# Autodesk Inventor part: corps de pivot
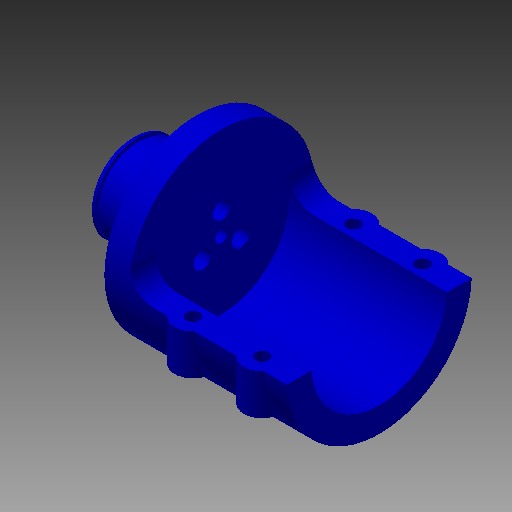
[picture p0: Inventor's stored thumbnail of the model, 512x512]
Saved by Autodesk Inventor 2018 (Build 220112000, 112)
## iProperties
Created: 2015-03
Part Number: corps de pivot
Material: Générique
Document SubType Name: Modeling
Designer: tjost
Density: 1 g/cm^3
Appearance: Par défaut
Author: tjost
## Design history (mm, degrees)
node "corps de pivot1"
node "corps de pivot"
node "Base1"
